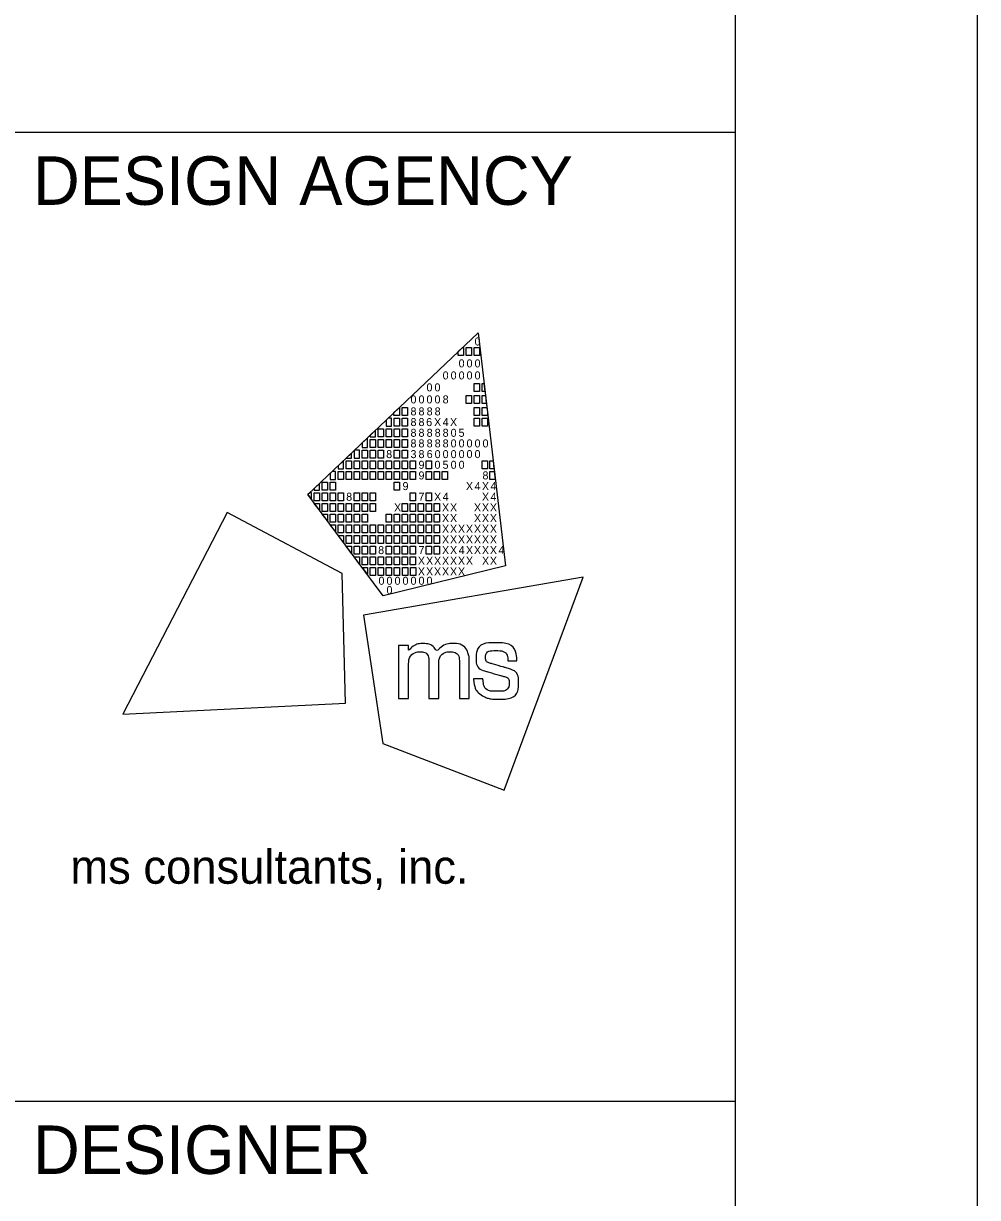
# Model space of a CAD drawing. Extents: x 0 to 34, y 0 to 22.
# Drawn here: x 32.03 to 34, y 2.301 to 4.724 of the extents above; entities that cross this region are included whole.
import ezdxf

# ---------------------------------------------------------------- set-up
doc = ezdxf.new("R2010")
doc.units = 0
for name, color, linetype in [('SH_Border', 7, 'Continuous'), ('SH_Cut_Line', 7, 'Continuous'), ('SH_Data', 7, 'Continuous'), ('SH_Text', 7, 'Continuous')]:
    doc.layers.add(name, color=color, linetype=linetype)

msp = doc.modelspace()

# ---------------------------------------------------------------- linework, layer by layer
at = {"layer": 'SH_Border'}
for p, q in [((32, 4.5), (33.5, 4.5)), ((32, 2.5), (33.5, 2.5))]:
    msp.add_line(p, q, dxfattribs=at)
msp.add_lwpolyline([(1.5, 21.5), (33.5, 21.5), (33.5, 0.5), (1.5, 0.5)], close=True, dxfattribs=at)
at = {"layer": 'SH_Cut_Line'}
msp.add_lwpolyline([(0, 0), (34, 0), (34, 22), (0, 22)], close=True, dxfattribs=at)
at = {"layer": 'SH_Data'}
msp.add_line((32.75, 3.5), (32.75, 3.5), dxfattribs=at)
at = {"layer": 'SH_Text'}
for p, q in [((32.6175, 3.7519), (32.9688, 4.0861)), ((32.9688, 4.0861), (32.9688, 4.0861)), ((32.9688, 4.0861), (33.0253, 3.6052)), ((32.773, 3.543), (32.6175, 3.7519)), ((33.0253, 3.6052), (32.773, 3.543))]:
    msp.add_line(p, q, dxfattribs=at)
for points in [[(32.9279, 4.0472), (32.9369, 4.0558), (32.9389, 4.0558), (32.9389, 4.0393), (32.9279, 4.0393)], [(32.9444, 4.0558), (32.9554, 4.0558), (32.9554, 4.0393), (32.9444, 4.0393)], [(32.9609, 4.0558), (32.9719, 4.0558), (32.9719, 4.0393), (32.9609, 4.0393)], [(32.9606, 3.9815), (32.9716, 3.9815), (32.9716, 3.965), (32.9606, 3.965)], [(32.9771, 3.9815), (32.9811, 3.9815), (32.983, 3.965), (32.9771, 3.965)], [(32.9441, 3.9567), (32.9551, 3.9567), (32.9551, 3.9402), (32.9441, 3.9402)], [(32.9606, 3.9567), (32.9716, 3.9567), (32.9716, 3.9402), (32.9606, 3.9402)], [(32.9771, 3.9567), (32.984, 3.9567), (32.9859, 3.9402), (32.9771, 3.9402)], [(32.7953, 3.9211), (32.8064, 3.9316), (32.8064, 3.9154), (32.7953, 3.9154)], [(32.8123, 3.9319), (32.8233, 3.9319), (32.8233, 3.9154), (32.8123, 3.9154)], [(32.9606, 3.9319), (32.9716, 3.9319), (32.9716, 3.9154), (32.9606, 3.9154)], [(32.9771, 3.9319), (32.9869, 3.9319), (32.9881, 3.9218), (32.9881, 3.9154), (32.9771, 3.9154)], [(32.7958, 3.9099), (32.8068, 3.9099), (32.8068, 3.8934), (32.7958, 3.8934)], [(32.8123, 3.9099), (32.8233, 3.9099), (32.8233, 3.8934), (32.8123, 3.8934)], [(32.9606, 3.9099), (32.9716, 3.9099), (32.9716, 3.8934), (32.9606, 3.8934)], [(32.9771, 3.9099), (32.9881, 3.9099), (32.9881, 3.8934), (32.9771, 3.8934)], [(32.7627, 3.8879), (32.7737, 3.8879), (32.7737, 3.8714), (32.7627, 3.8714)], [(32.7793, 3.8879), (32.7903, 3.8879), (32.7903, 3.8714), (32.7793, 3.8714)], [(32.7958, 3.8879), (32.8068, 3.8879), (32.8068, 3.8714), (32.7958, 3.8714)], [(32.8123, 3.8879), (32.8233, 3.8879), (32.8233, 3.8714), (32.8123, 3.8714)], [(32.7462, 3.8659), (32.7572, 3.8659), (32.7572, 3.8494), (32.7462, 3.8494)], [(32.7627, 3.8659), (32.7737, 3.8659), (32.7737, 3.8494), (32.7627, 3.8494)], [(32.7793, 3.8659), (32.7903, 3.8659), (32.7903, 3.8494), (32.7793, 3.8494)], [(32.7958, 3.8659), (32.8068, 3.8659), (32.8068, 3.8494), (32.7958, 3.8494)], [(32.8123, 3.8659), (32.8233, 3.8659), (32.8233, 3.8494), (32.8123, 3.8494)], [(32.7297, 3.8439), (32.7407, 3.8439), (32.7407, 3.8273), (32.7297, 3.8273)], [(32.7462, 3.8439), (32.7572, 3.8439), (32.7572, 3.8273), (32.7462, 3.8273)], [(32.7627, 3.8439), (32.7737, 3.8439), (32.7737, 3.8273), (32.7627, 3.8273)], [(32.7958, 3.8439), (32.8068, 3.8439), (32.8068, 3.8273), (32.7958, 3.8273)], [(32.8123, 3.8439), (32.8233, 3.8439), (32.8233, 3.8273), (32.8123, 3.8273)], [(32.6967, 3.8218), (32.7077, 3.8218), (32.7077, 3.8053), (32.6967, 3.8053)], [(32.7132, 3.8218), (32.7242, 3.8218), (32.7242, 3.8053), (32.7132, 3.8053)], [(32.7297, 3.8218), (32.7407, 3.8218), (32.7407, 3.8053), (32.7297, 3.8053)], [(32.7462, 3.8218), (32.7572, 3.8218), (32.7572, 3.8053), (32.7462, 3.8053)], [(32.7627, 3.8218), (32.7737, 3.8218), (32.7737, 3.8053), (32.7627, 3.8053)], [(32.7793, 3.8218), (32.7903, 3.8218), (32.7903, 3.8053), (32.7793, 3.8053)], [(32.7958, 3.8218), (32.8068, 3.8218), (32.8068, 3.8053), (32.7958, 3.8053)], [(32.8123, 3.8218), (32.8233, 3.8218), (32.8233, 3.8053), (32.8123, 3.8053)], [(32.8288, 3.8218), (32.8398, 3.8218), (32.8398, 3.8053), (32.8288, 3.8053)], [(32.8618, 3.8218), (32.8728, 3.8218), (32.8728, 3.8053), (32.8618, 3.8053)], [(32.9771, 3.8218), (32.9881, 3.8218), (32.9881, 3.8053), (32.9771, 3.8053)], [(32.9935, 3.8218), (32.9998, 3.8218), (33.0018, 3.8053), (32.9935, 3.8053)], [(32.6802, 3.7998), (32.6912, 3.7998), (32.6912, 3.7833), (32.6802, 3.7833)], [(32.6967, 3.7998), (32.7077, 3.7998), (32.7077, 3.7833), (32.6967, 3.7833)], [(32.7132, 3.7998), (32.7242, 3.7998), (32.7242, 3.7833), (32.7132, 3.7833)], [(32.7297, 3.7998), (32.7407, 3.7998), (32.7407, 3.7833), (32.7297, 3.7833)], [(32.7462, 3.7998), (32.7572, 3.7998), (32.7572, 3.7833), (32.7462, 3.7833)], [(32.7627, 3.7998), (32.7737, 3.7998), (32.7737, 3.7833), (32.7627, 3.7833)], [(32.7793, 3.7998), (32.7903, 3.7998), (32.7903, 3.7833), (32.7793, 3.7833)], [(32.7958, 3.7998), (32.8068, 3.7998), (32.8068, 3.7833), (32.7958, 3.7833)], [(32.8123, 3.7998), (32.8233, 3.7998), (32.8233, 3.7833), (32.8123, 3.7833)], [(32.8288, 3.7998), (32.8398, 3.7998), (32.8398, 3.7833), (32.8288, 3.7833)], [(32.8618, 3.7998), (32.8728, 3.7998), (32.8728, 3.7833), (32.8618, 3.7833)], [(32.8783, 3.7998), (32.8893, 3.7998), (32.8893, 3.7833), (32.8783, 3.7833)], [(32.8947, 3.7998), (32.9057, 3.7998), (32.9057, 3.7833), (32.8947, 3.7833)], [(32.9935, 3.7998), (33.0024, 3.7998), (33.0044, 3.7833), (32.9935, 3.7833)], [(32.6306, 3.7558), (32.6416, 3.7558), (32.6416, 3.7393), (32.6306, 3.7393)], [(32.6471, 3.7778), (32.6581, 3.7778), (32.6581, 3.7613), (32.6471, 3.7613)], [(32.6471, 3.7558), (32.6581, 3.7558), (32.6581, 3.7393), (32.6471, 3.7393)], [(32.6637, 3.7778), (32.6747, 3.7778), (32.6747, 3.7613), (32.6637, 3.7613)], [(32.6637, 3.7558), (32.6747, 3.7558), (32.6747, 3.7393), (32.6637, 3.7393)], [(32.6802, 3.7558), (32.6912, 3.7558), (32.6912, 3.7393), (32.6802, 3.7393)], [(32.7132, 3.7558), (32.7242, 3.7558), (32.7242, 3.7393), (32.7132, 3.7393)], [(32.7297, 3.7558), (32.7407, 3.7558), (32.7407, 3.7393), (32.7297, 3.7393)], [(32.7462, 3.7558), (32.7572, 3.7558), (32.7572, 3.7393), (32.7462, 3.7393)], [(32.7958, 3.7778), (32.8068, 3.7778), (32.8068, 3.7613), (32.7958, 3.7613)], [(32.8288, 3.7558), (32.8398, 3.7558), (32.8398, 3.7393), (32.8288, 3.7393)], [(32.8618, 3.7558), (32.8728, 3.7558), (32.8728, 3.7393), (32.8618, 3.7393)], [(32.6306, 3.7338), (32.6416, 3.7338), (32.6416, 3.72)], [(32.6471, 3.7338), (32.6581, 3.7338), (32.6581, 3.7173), (32.6471, 3.7173)], [(32.6637, 3.7338), (32.6747, 3.7338), (32.6747, 3.7173), (32.6637, 3.7173)], [(32.6802, 3.7338), (32.6912, 3.7338), (32.6912, 3.7173), (32.6802, 3.7173)], [(32.6967, 3.7338), (32.7077, 3.7338), (32.7077, 3.7173), (32.6967, 3.7173)], [(32.7132, 3.7338), (32.7242, 3.7338), (32.7242, 3.7173), (32.7132, 3.7173)], [(32.7297, 3.7338), (32.7407, 3.7338), (32.7407, 3.7173), (32.7297, 3.7173)], [(32.7462, 3.7338), (32.7572, 3.7338), (32.7572, 3.7173), (32.7462, 3.7173)], [(32.8123, 3.7338), (32.8233, 3.7338), (32.8233, 3.7173), (32.8123, 3.7173)], [(32.8288, 3.7338), (32.8398, 3.7338), (32.8398, 3.7173), (32.8288, 3.7173)], [(32.8453, 3.7338), (32.8563, 3.7338), (32.8563, 3.7173), (32.8453, 3.7173)], [(32.8618, 3.7338), (32.8728, 3.7338), (32.8728, 3.7173), (32.8618, 3.7173)], [(32.8783, 3.7338), (32.8893, 3.7338), (32.8893, 3.7173), (32.8783, 3.7173)], [(32.6471, 3.7117), (32.6581, 3.7117), (32.6581, 3.698)], [(32.6637, 3.7117), (32.6747, 3.7117), (32.6747, 3.6952), (32.6637, 3.6952)], [(32.6802, 3.7117), (32.6912, 3.7117), (32.6912, 3.6952), (32.6802, 3.6952)], [(32.6967, 3.7117), (32.7077, 3.7117), (32.7077, 3.6952), (32.6967, 3.6952)], [(32.7132, 3.7117), (32.7242, 3.7117), (32.7242, 3.6952), (32.7132, 3.6952)], [(32.7297, 3.7117), (32.7407, 3.7117), (32.7407, 3.6952), (32.7297, 3.6952)], [(32.7793, 3.7117), (32.7903, 3.7117), (32.7903, 3.6952), (32.7793, 3.6952)], [(32.7958, 3.7117), (32.8068, 3.7117), (32.8068, 3.6952), (32.7958, 3.6952)], [(32.8123, 3.7117), (32.8233, 3.7117), (32.8233, 3.6952), (32.8123, 3.6952)], [(32.8288, 3.7117), (32.8398, 3.7117), (32.8398, 3.6952), (32.8288, 3.6952)], [(32.8453, 3.7117), (32.8563, 3.7117), (32.8563, 3.6952), (32.8453, 3.6952)], [(32.8618, 3.7117), (32.8728, 3.7117), (32.8728, 3.6952), (32.8618, 3.6952)], [(32.8783, 3.7117), (32.8893, 3.7117), (32.8893, 3.6952), (32.8783, 3.6952)], [(32.6637, 3.6897), (32.6747, 3.6897), (32.6747, 3.676)], [(32.6747, 3.6897), (32.6747, 3.6897), (32.6747, 3.6897)], [(32.6802, 3.6897), (32.6912, 3.6897), (32.6912, 3.6732), (32.6802, 3.6732)], [(32.6967, 3.6897), (32.7077, 3.6897), (32.7077, 3.6732), (32.6967, 3.6732)], [(32.7132, 3.6897), (32.7242, 3.6897), (32.7242, 3.6732), (32.7132, 3.6732)], [(32.7297, 3.6897), (32.7407, 3.6897), (32.7407, 3.6732), (32.7297, 3.6732)], [(32.7462, 3.6897), (32.7572, 3.6897), (32.7572, 3.6732), (32.7462, 3.6732)], [(32.7627, 3.6897), (32.7737, 3.6897), (32.7737, 3.6732), (32.7627, 3.6732)], [(32.7793, 3.6897), (32.7903, 3.6897), (32.7903, 3.6732), (32.7793, 3.6732)], [(32.7958, 3.6897), (32.8068, 3.6897), (32.8068, 3.6732), (32.7958, 3.6732)], [(32.8123, 3.6897), (32.8233, 3.6897), (32.8233, 3.6732), (32.8123, 3.6732)], [(32.8288, 3.6897), (32.8398, 3.6897), (32.8398, 3.6732), (32.8288, 3.6732)], [(32.8453, 3.6897), (32.8563, 3.6897), (32.8563, 3.6732), (32.8453, 3.6732)], [(32.8618, 3.6897), (32.8728, 3.6897), (32.8728, 3.6732), (32.8618, 3.6732)], [(32.8783, 3.6897), (32.8893, 3.6897), (32.8893, 3.6732), (32.8783, 3.6732)], [(32.6802, 3.6677), (32.6912, 3.6677), (32.6912, 3.654)], [(32.6967, 3.6677), (32.7077, 3.6677), (32.7077, 3.6512), (32.6967, 3.6512)], [(32.7132, 3.6677), (32.7242, 3.6677), (32.7242, 3.6512), (32.7132, 3.6512)], [(32.7297, 3.6677), (32.7407, 3.6677), (32.7407, 3.6512), (32.7297, 3.6512)], [(32.7462, 3.6677), (32.7572, 3.6677), (32.7572, 3.6512), (32.7462, 3.6512)], [(32.7627, 3.6677), (32.7737, 3.6677), (32.7737, 3.6512), (32.7627, 3.6512)], [(32.7793, 3.6677), (32.7903, 3.6677), (32.7903, 3.6512), (32.7793, 3.6512)], [(32.7958, 3.6677), (32.8068, 3.6677), (32.8068, 3.6512), (32.7958, 3.6512)], [(32.8123, 3.6677), (32.8233, 3.6677), (32.8233, 3.6512), (32.8123, 3.6512)], [(32.8288, 3.6677), (32.8398, 3.6677), (32.8398, 3.6512), (32.8288, 3.6512)], [(32.8453, 3.6677), (32.8563, 3.6677), (32.8563, 3.6512), (32.8453, 3.6512)], [(32.8618, 3.6677), (32.8728, 3.6677), (32.8728, 3.6512), (32.8618, 3.6512)], [(32.8783, 3.6677), (32.8893, 3.6677), (32.8893, 3.6512), (32.8783, 3.6512)], [(32.7077, 3.6305), (32.6965, 3.6457), (32.7077, 3.6457)], [(32.7132, 3.6457), (32.7242, 3.6457), (32.7242, 3.6292), (32.7132, 3.6292)], [(32.7297, 3.6457), (32.7407, 3.6457), (32.7407, 3.6292), (32.7297, 3.6292)], [(32.7462, 3.6457), (32.7572, 3.6457), (32.7572, 3.6292), (32.7462, 3.6292)], [(32.7793, 3.6457), (32.7903, 3.6457), (32.7903, 3.6292), (32.7793, 3.6292)], [(32.7958, 3.6457), (32.8068, 3.6457), (32.8068, 3.6292), (32.7958, 3.6292)], [(32.8123, 3.6457), (32.8233, 3.6457), (32.8233, 3.6292), (32.8123, 3.6292)], [(32.8288, 3.6457), (32.8398, 3.6457), (32.8398, 3.6292), (32.8288, 3.6292)], [(32.8618, 3.6457), (32.8728, 3.6457), (32.8728, 3.6292), (32.8618, 3.6292)], [(32.8783, 3.6457), (32.8893, 3.6457), (32.8893, 3.6292), (32.8783, 3.6292)], [(32.724, 3.6082), (32.7132, 3.6237), (32.7242, 3.6237)], [(32.7297, 3.6237), (32.7407, 3.6237), (32.7407, 3.6072), (32.7297, 3.6072)], [(32.7462, 3.6237), (32.7572, 3.6237), (32.7572, 3.6072), (32.7462, 3.6072)], [(32.7627, 3.6237), (32.7737, 3.6237), (32.7737, 3.6072), (32.7627, 3.6072)], [(32.7793, 3.6237), (32.7903, 3.6237), (32.7903, 3.6072), (32.7793, 3.6072)], [(32.7958, 3.6237), (32.8068, 3.6237), (32.8068, 3.6072), (32.7958, 3.6072)], [(32.8123, 3.6237), (32.8233, 3.6237), (32.8233, 3.6072), (32.8123, 3.6072)], [(32.8288, 3.6237), (32.8398, 3.6237), (32.8398, 3.6072), (32.8288, 3.6072)], [(32.7302, 3.6017), (32.7407, 3.6017), (32.7408, 3.5875)], [(32.7463, 3.6017), (32.7573, 3.6017), (32.7573, 3.5852), (32.7463, 3.5852)], [(32.763, 3.6017), (32.774, 3.6017), (32.774, 3.5852), (32.763, 3.5852)], [(32.7794, 3.6017), (32.7904, 3.6017), (32.7904, 3.5852), (32.7794, 3.5852)], [(32.796, 3.6017), (32.807, 3.6017), (32.807, 3.5852), (32.796, 3.5852)], [(32.8129, 3.6017), (32.8239, 3.6017), (32.8239, 3.5851), (32.8129, 3.5851)], [(32.8296, 3.6017), (32.8406, 3.6017), (32.8406, 3.5851), (32.8296, 3.5851)]]:
    msp.add_lwpolyline(points, close=True, dxfattribs=at)
for points in [[(32.7903, 3.9099), (32.7836, 3.9099), (32.7793, 3.9058), (32.7793, 3.8934), (32.7903, 3.8934), (32.7903, 3.9099)], [(32.7572, 3.8849), (32.7462, 3.8744), (32.7462, 3.8714), (32.7572, 3.8714), (32.7572, 3.8849)], [(32.7407, 3.8691), (32.7297, 3.8587), (32.7297, 3.8494), (32.7407, 3.8494), (32.7407, 3.8691)], [(32.7077, 3.8377), (32.6968, 3.8273), (32.7077, 3.8273), (32.7077, 3.8377)], [(32.7242, 3.8439), (32.7141, 3.8439), (32.7132, 3.843), (32.7132, 3.8273), (32.7242, 3.8273), (32.7242, 3.8439)], [(32.6912, 3.822), (32.6802, 3.8115), (32.6802, 3.8053), (32.6912, 3.8053), (32.6912, 3.822)], [(32.6747, 3.7998), (32.6679, 3.7998), (32.6637, 3.7958), (32.6637, 3.7833), (32.6747, 3.7833), (32.6747, 3.7998)], [(32.6251, 3.7558), (32.6216, 3.7558), (32.6175, 3.7519), (32.6251, 3.7417), (32.6251, 3.7558)], [(32.6416, 3.7749), (32.6306, 3.7644), (32.6306, 3.7613), (32.6416, 3.7613), (32.6416, 3.7749)], [(32.4512, 3.7149), (32.2359, 3.2988), (32.6956, 3.3215), (32.6884, 3.5892), (32.4512, 3.7149)], [(33.0229, 3.1422), (33.1859, 3.5814), (32.7324, 3.5029), (32.7722, 3.2381), (33.0229, 3.1422)]]:
    msp.add_lwpolyline(points, dxfattribs=at)
for points in [[(32.8048, 3.3315), (32.8048, 3.3315), (32.8048, 3.4409), (32.8048, 3.4409), (32.8048, 3.4409), (32.8255, 3.4409), (32.8255, 3.4409), (32.8255, 3.4409), (32.8255, 3.4297), (32.8255, 3.4297), (32.8346, 3.4399), (32.8457, 3.4445), (32.8555, 3.4445), (32.8688, 3.4445), (32.8791, 3.4372), (32.8837, 3.4266), (32.8915, 3.4381), (32.905, 3.4446), (32.9166, 3.4446), (32.9325, 3.4446), (32.9451, 3.435), (32.9494, 3.4213), (32.9494, 3.4212), (32.9494, 3.4212), (32.9494, 3.4212), (32.9501, 3.419), (32.9506, 3.4172), (32.9506, 3.4071), (32.9506, 3.4071), (32.9506, 3.3314), (32.9506, 3.3314), (32.9506, 3.3314), (32.9303, 3.3314), (32.9303, 3.3314), (32.9303, 3.3314), (32.9303, 3.4048), (32.9303, 3.4048), (32.9303, 3.4201), (32.9219, 3.4274), (32.911, 3.4274), (32.8995, 3.4274), (32.8879, 3.4171), (32.8879, 3.4001), (32.8879, 3.4001), (32.8879, 3.3315), (32.8879, 3.3315), (32.8879, 3.3315), (32.8674, 3.3315), (32.8674, 3.3315), (32.8674, 3.3315), (32.8674, 3.4059), (32.8674, 3.4059), (32.8674, 3.4203), (32.8588, 3.4274), (32.8496, 3.4274), (32.8384, 3.4274), (32.8254, 3.417), (32.8254, 3.3962), (32.8254, 3.3962), (32.8254, 3.3315), (32.8254, 3.3315), (32.8254, 3.3315), (32.8048, 3.3315), (32.8048, 3.3315)], [(32.9595, 3.3709), (32.9595, 3.3709), (32.9595, 3.3717), (32.9595, 3.3717), (32.9595, 3.3717), (32.9603, 3.3717), (32.9603, 3.3717), (32.9603, 3.3717), (32.9783, 3.3717), (32.9783, 3.3717), (32.9783, 3.3717), (32.9789, 3.3717), (32.9789, 3.3717), (32.9789, 3.3717), (32.979, 3.371), (32.979, 3.371), (32.9803, 3.3554), (32.9887, 3.346), (33.009, 3.346), (33.0273, 3.346), (33.0333, 3.3554), (33.0333, 3.3631), (33.0333, 3.3732), (33.0256, 3.3758), (33.0175, 3.378), (33.0175, 3.378), (32.987, 3.3867), (32.987, 3.3867), (32.972, 3.3909), (32.9648, 3.4019), (32.9648, 3.4142), (32.9648, 3.4303), (32.9768, 3.4462), (33.0052, 3.4462), (33.0348, 3.4462), (33.0489, 3.4285), (33.0489, 3.4095), (33.0489, 3.4095), (33.0489, 3.4087), (33.0489, 3.4087), (33.0489, 3.4087), (33.0482, 3.4087), (33.0482, 3.4087), (33.0482, 3.4087), (33.0312, 3.4087), (33.0312, 3.4087), (33.0312, 3.4087), (33.0305, 3.4087), (33.0305, 3.4087), (33.0305, 3.4087), (33.0305, 3.4094), (33.0305, 3.4094), (33.0301, 3.4208), (33.0226, 3.43), (33.0056, 3.43), (32.9891, 3.43), (32.9843, 3.4218), (32.9843, 3.4157), (32.9843, 3.4108), (32.9869, 3.4059), (32.9959, 3.4033), (32.9959, 3.4033), (33.0255, 3.3948), (33.0255, 3.3948), (33.0462, 3.3889), (33.0527, 3.3777), (33.0527, 3.3639), (33.0527, 3.3462), (33.041, 3.3298), (33.0087, 3.3298), (32.9952, 3.3298), (32.9877, 3.3321), (32.9823, 3.3348), (32.969, 3.3414), (32.9609, 3.3536), (32.9595, 3.3709)]]:
    msp.add_open_spline(points, degree=3, dxfattribs=at)

# ---------------------------------------------------------------- texts
at = {"layer": 'SH_Border'}
msp.add_text('ms consultants, inc.', height=0.07, rotation=360, dxfattribs=at).set_placement((32.1273, 2.9489))
at = {"layer": 'SH_Data'}
for s, p in [('DESIGN AGENCY', (32.05, 4.35)), ('DESIGNER', (32.05, 2.35))]:
    msp.add_text(s, height=0.1, dxfattribs=at).set_placement(p)
at = {"layer": 'SH_Text'}
for s, p in [('0', (32.9617, 4.0597)), ('0', (32.9288, 4.0145)), ('0', (32.9452, 4.0145)), ('0', (32.9617, 4.0145)), ('0', (32.8958, 3.9897)), ('0', (32.9123, 3.9897)), ('0', (32.9288, 3.9897)), ('0', (32.9452, 3.9897)), ('0', (32.9617, 3.9897)), ('0', (32.8625, 3.965)), ('0', (32.879, 3.965)), ('0', (32.8295, 3.9402)), ('0', (32.846, 3.9402)), ('0', (32.8625, 3.9402)), ('0', (32.879, 3.9402)), ('8', (32.8958, 3.9402)), ('8', (32.8295, 3.9154)), ('8', (32.846, 3.9154)), ('8', (32.8628, 3.9154)), ('8', (32.8793, 3.9154)), ('8', (32.8295, 3.8934)), ('8', (32.846, 3.8934)), ('6', (32.8618, 3.8934)), ('X', (32.8781, 3.8934)), ('4', (32.8958, 3.8934)), ('X', (32.911, 3.8934)), ('8', (32.8295, 3.8713)), ('8', (32.846, 3.8713)), ('8', (32.8628, 3.8713)), ('8', (32.8794, 3.8713)), ('8', (32.8958, 3.8713)), ('0', (32.9123, 3.8713)), ('5', (32.9287, 3.8713)), ('8', (32.8295, 3.8494)), ('8', (32.846, 3.8494)), ('8', (32.8628, 3.8494)), ('8', (32.8794, 3.8494)), ('8', (32.8958, 3.8494)), ('0', (32.9123, 3.8494)), ('0', (32.9288, 3.8494)), ('0', (32.9452, 3.8494)), ('0', (32.9617, 3.8494)), ('0', (32.9782, 3.8494)), ('8', (32.7793, 3.8273)), ('3', (32.8295, 3.8273)), ('8', (32.846, 3.8273)), ('6', (32.8629, 3.8273)), ('0', (32.8793, 3.8273)), ('0', (32.8958, 3.8273)), ('0', (32.9123, 3.8273)), ('0', (32.9288, 3.8273)), ('0', (32.9452, 3.8273)), ('0', (32.9617, 3.8273)), ('9', (32.846, 3.8053)), ('0', (32.879, 3.8053)), ('5', (32.8957, 3.8053)), ('0', (32.9123, 3.8053)), ('0', (32.9288, 3.8053)), ('9', (32.846, 3.7833)), ('8', (32.9781, 3.7833)), ('8', (32.6967, 3.7393)), ('9', (32.813, 3.7613)), ('7', (32.846, 3.7393)), ('X', (32.8781, 3.7393)), ('4', (32.8958, 3.7393)), ('X', (32.9439, 3.7613)), ('4', (32.9617, 3.7613)), ('X', (32.9769, 3.7613)), ('X', (32.9769, 3.7393)), ('4', (32.9946, 3.7613)), ('4', (32.9946, 3.7393)), ('X', (32.7955, 3.7173)), ('X', (32.8945, 3.7173)), ('X', (32.911, 3.7173)), ('X', (32.9604, 3.7173)), ('X', (32.9769, 3.7173)), ('X', (32.9933, 3.7173)), ('X', (32.8945, 3.6952)), ('X', (32.911, 3.6952)), ('X', (32.9604, 3.6952)), ('X', (32.9769, 3.6952)), ('X', (32.9933, 3.6952)), ('X', (32.8945, 3.6732)), ('X', (32.911, 3.6732)), ('X', (32.9274, 3.6732)), ('X', (32.9439, 3.6732)), ('X', (32.9604, 3.6732)), ('X', (32.9769, 3.6732)), ('X', (32.9933, 3.6732)), ('X', (32.8945, 3.6512)), ('X', (32.911, 3.6512)), ('X', (32.9274, 3.6512)), ('X', (32.9439, 3.6512)), ('X', (32.9604, 3.6512)), ('X', (32.9769, 3.6512)), ('X', (32.9933, 3.6512)), ('8', (32.7627, 3.6292)), ('7', (32.846, 3.6292)), ('X', (32.8945, 3.6292)), ('X', (32.911, 3.6292)), ('4', (32.9288, 3.6292)), ('X', (32.9439, 3.6292)), ('X', (32.9604, 3.6292)), ('X', (32.9769, 3.6292)), ('X', (32.9933, 3.6292)), ('4', (33.0111, 3.6292)), ('X', (32.8447, 3.6072)), ('X', (32.8616, 3.6072)), ('X', (32.878, 3.6072)), ('X', (32.8945, 3.6072)), ('X', (32.911, 3.6072)), ('X', (32.9274, 3.6072)), ('X', (32.9439, 3.6072)), ('X', (32.9771, 3.6072)), ('X', (32.9933, 3.6072)), ('X', (32.8447, 3.5851)), ('X', (32.8616, 3.5851)), ('X', (32.878, 3.5851)), ('X', (32.8945, 3.5851)), ('X', (32.911, 3.5851)), ('X', (32.9274, 3.5851)), ('0', (32.7634, 3.5659)), ('0', (32.7799, 3.5659)), ('0', (32.7799, 3.5467)), ('0', (32.7965, 3.5659)), ('0', (32.813, 3.5659)), ('0', (32.8295, 3.5659)), ('0', (32.846, 3.5659)), ('0', (32.8625, 3.5659))]:
    msp.add_text(s, height=0.0165, rotation=360, dxfattribs=at).set_placement(p)

doc.saveas('drawing.dxf')
